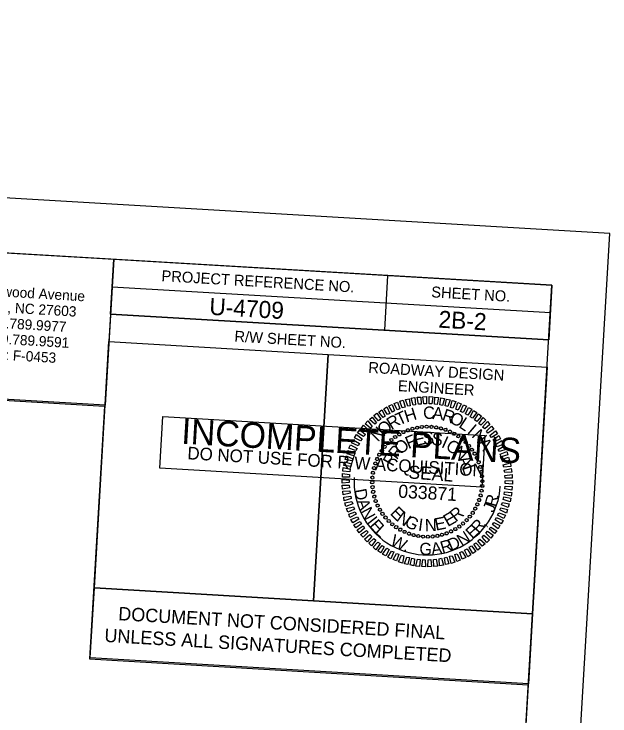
# Model space of a CAD drawing. Extents: x 2012744 to 2013625, y 444638 to 445237.
# Drawn here: x 2013488.7 to 2013624.5, y 445076.8 to 445236.8 of the extents above; entities that cross this region are included whole.
import ezdxf

# ---------------------------------------------------------------- set-up
doc = ezdxf.new("R2010")
doc.units = 0
for name, color, linetype in [('Old_Level_2', 7, 'Continuous'), ('Old_Level_58', 7, 'Continuous'), ('Scratch_Level_0', 7, 'Continuous'), ('Sheet Clip Boundary CELL', 7, 'Continuous'), ('Sheet Data Field CELL', 7, 'Continuous'), ('Sheet Plan And Profile CELL', 7, 'Continuous'), ('Sheet Plot Border Outside CELL', 7, 'Continuous'), ('Sheet Professional Seal CELL', 7, 'Continuous'), ('Sheet Profile Grid Minor CELL', 7, 'Continuous'), ('Sheet Sticker Exception Certification CELL', 7, 'Continuous'), ('Sheet Sticker Incomplete CELL', 7, 'Continuous')]:
    doc.layers.add(name, color=color, linetype=linetype)

msp = doc.modelspace()

# ---------------------------------------------------------------- linework, layer by layer
at = {"layer": 'Old_Level_58'}
msp.add_lwpolyline([(2013411.6, 445186.8), (2013511.45, 445180.92), (2013509.49, 445147.63), (2013409.64, 445153.51)], close=True, dxfattribs=at)
at = {"layer": 'Scratch_Level_0'}
msp.add_arc((2013582.88, 445130.21), 16.68, 176.6264, 356.6264, dxfattribs=at)
at = {"layer": 'Sheet Clip Boundary CELL'}
for points in [[(2013605.95, 445084.18), (2013506.09, 445090.07), (2013509.49, 445147.63), (2013409.64, 445153.51), (2013411.6, 445186.8), (2012862.6, 445219.16), (2012831.71, 444695.07), (2013580.41, 444650.94)], [(2012832.37, 444695.56), (2012863.22, 445218.85), (2013411.41, 445186.54), (2013409.45, 445153.34), (2013509.31, 445147.45), (2013505.92, 445089.85), (2013605.86, 445083.96), (2013580.34, 444651.05)]]:
    msp.add_lwpolyline(points, close=True, dxfattribs=at)
at = {"layer": 'Sheet Plan And Profile CELL'}
for p, q in [((2013573.86, 445177.21), (2013573.13, 445164.73)), ((2013511.08, 445174.65), (2013610.93, 445168.77)), ((2013510.71, 445168.41), (2013510.34, 445162.17)), ((2013510.71, 445168.41), (2013610.56, 445162.53)), ((2013560.28, 445159.23), (2013556.97, 445103.1))]:
    msp.add_line(p, q, dxfattribs=at)
for points in [[(2013611.3, 445175.03), (2012862.6, 445219.16), (2012831.71, 444695.07), (2013580.41, 444650.94)], [(2013511.45, 445180.92), (2013611.3, 445175.03), (2013610.56, 445162.53), (2013510.71, 445168.41)], [(2013510.34, 445162.17), (2013560.28, 445159.23), (2013556.97, 445103.08), (2013507.03, 445106.02)], [(2013560.28, 445159.23), (2013610.2, 445156.29), (2013606.89, 445100.13), (2013556.97, 445103.08)]]:
    msp.add_lwpolyline(points, close=True, dxfattribs=at)
at = {"layer": 'Sheet Plot Border Outside CELL'}
msp.add_lwpolyline([(2012743.62, 444687.74), (2013592.15, 444637.73), (2013624.51, 445186.77), (2012775.99, 445236.79)], close=True, dxfattribs=at)
at = {"layer": 'Sheet Professional Seal CELL'}
for p, q in [((2013577.47, 445141.52), (2013577.47, 445141.52)), ((2013578.47, 445141.96), (2013578.47, 445141.96)), ((2013579.49, 445142.3), (2013579.49, 445142.3)), ((2013580.56, 445142.54), (2013580.56, 445142.54)), ((2013581.67, 445142.68), (2013581.67, 445142.68)), ((2013582.75, 445142.76), (2013582.75, 445142.76)), ((2013583.85, 445142.72), (2013583.85, 445142.72)), ((2013584.94, 445142.58), (2013584.94, 445142.58)), ((2013586, 445142.35), (2013586, 445142.35)), ((2013587.04, 445142.06), (2013587.04, 445142.06)), ((2013588.07, 445141.65), (2013588.07, 445141.65)), ((2013575.57, 445140.43), (2013575.57, 445140.43)), ((2013576.48, 445141), (2013576.48, 445141)), ((2013589.04, 445141.14), (2013589.04, 445141.14)), ((2013589.98, 445140.58), (2013589.98, 445140.58)), ((2013590.84, 445139.91), (2013590.84, 445139.91)), ((2013573.91, 445139), (2013573.91, 445139)), ((2013574.71, 445139.73), (2013574.71, 445139.73)), ((2013591.68, 445139.18), (2013591.68, 445139.18)), ((2013592.41, 445138.39), (2013592.41, 445138.39)), ((2013572.51, 445137.31), (2013572.51, 445137.31)), ((2013573.19, 445138.17), (2013573.19, 445138.17)), ((2013593.11, 445137.52), (2013593.11, 445137.52)), ((2013593.68, 445136.61), (2013593.68, 445136.61)), ((2013571.45, 445135.39), (2013571.45, 445135.39)), ((2013571.95, 445136.36), (2013571.95, 445136.36)), ((2013594.2, 445135.63), (2013594.2, 445135.63)), ((2013571.03, 445134.36), (2013571.03, 445134.36)), ((2013594.64, 445134.62), (2013594.64, 445134.62)), ((2013594.98, 445133.6), (2013594.98, 445133.6)), ((2013570.51, 445132.26), (2013570.51, 445132.26)), ((2013570.75, 445133.33), (2013570.75, 445133.33)), ((2013595.22, 445132.54), (2013595.22, 445132.54)), ((2013570.37, 445131.17), (2013570.37, 445131.17)), ((2013582.88, 445130.21), (2013582.88, 445130.21)), ((2013595.35, 445131.43), (2013595.35, 445131.43)), ((2013595.44, 445130.34), (2013595.44, 445130.34)), ((2013570.33, 445130.07), (2013570.33, 445130.07)), ((2013570.42, 445128.99), (2013570.42, 445128.99)), ((2013595.4, 445129.24), (2013595.4, 445129.24)), ((2013570.55, 445127.88), (2013570.55, 445127.88)), ((2013595.02, 445127.09), (2013595.02, 445127.09)), ((2013595.26, 445128.15), (2013595.26, 445128.15)), ((2013570.79, 445126.81), (2013570.79, 445126.81)), ((2013571.13, 445125.79), (2013571.13, 445125.79)), ((2013594.74, 445126.05), (2013594.74, 445126.05)), ((2013571.57, 445124.79), (2013571.57, 445124.79)), ((2013572.09, 445123.81), (2013572.09, 445123.81)), ((2013593.82, 445124.05), (2013593.82, 445124.05)), ((2013594.32, 445125.03), (2013594.32, 445125.03)), ((2013572.66, 445122.9), (2013572.66, 445122.9)), ((2013592.58, 445122.25), (2013592.58, 445122.25)), ((2013593.26, 445123.11), (2013593.26, 445123.11)), ((2013573.36, 445122.03), (2013573.36, 445122.03)), ((2013574.09, 445121.23), (2013574.09, 445121.23)), ((2013591.06, 445120.68), (2013591.06, 445120.68)), ((2013591.86, 445121.41), (2013591.86, 445121.41)), ((2013574.93, 445120.51), (2013574.93, 445120.51)), ((2013575.79, 445119.83), (2013575.79, 445119.83)), ((2013576.73, 445119.28), (2013576.73, 445119.28)), ((2013589.29, 445119.41), (2013589.29, 445119.41)), ((2013590.2, 445119.98), (2013590.2, 445119.98)), ((2013577.7, 445118.77), (2013577.7, 445118.77)), ((2013578.73, 445118.36), (2013578.73, 445118.36)), ((2013579.77, 445118.07), (2013579.77, 445118.07)), ((2013580.83, 445117.83), (2013580.83, 445117.83)), ((2013581.92, 445117.69), (2013581.92, 445117.69)), ((2013583.02, 445117.65), (2013583.02, 445117.65)), ((2013584.1, 445117.74), (2013584.1, 445117.74)), ((2013585.21, 445117.87), (2013585.21, 445117.87)), ((2013586.28, 445118.11), (2013586.28, 445118.11)), ((2013587.3, 445118.45), (2013587.3, 445118.45)), ((2013588.3, 445118.89), (2013588.3, 445118.89))]:
    msp.add_line(p, q, dxfattribs=at)
for points in [[(2013580.87, 445147.86), (2013580.56, 445149.48), (2013581.39, 445149.5), (2013581.47, 445147.9)], [(2013582.08, 445147.94), (2013581.9, 445149.55), (2013582.75, 445149.6), (2013582.68, 445147.98)], [(2013583.33, 445147.99), (2013583.3, 445149.62), (2013584.12, 445149.54), (2013583.93, 445147.93)], [(2013584.53, 445147.89), (2013584.62, 445149.51), (2013585.45, 445149.44), (2013585.13, 445147.83)], [(2013574.96, 445146.08), (2013574.11, 445147.48), (2013574.91, 445147.83), (2013575.45, 445146.35)], [(2013576.06, 445146.61), (2013575.35, 445148.06), (2013576.14, 445148.36), (2013576.63, 445146.8)], [(2013577.19, 445147.07), (2013576.63, 445148.56), (2013577.4, 445148.81), (2013577.83, 445147.18)], [(2013578.44, 445147.4), (2013577.95, 445148.93), (2013578.74, 445149.11), (2013578.97, 445147.54)], [(2013579.66, 445147.65), (2013579.22, 445149.26), (2013580.08, 445149.38), (2013580.19, 445147.75)], [(2013585.77, 445147.74), (2013585.97, 445149.36), (2013586.78, 445149.16), (2013586.36, 445147.61)], [(2013586.96, 445147.47), (2013587.28, 445149.06), (2013588.09, 445148.88), (2013587.55, 445147.36)], [(2013588.21, 445147.12), (2013588.56, 445148.73), (2013589.4, 445148.48), (2013588.73, 445146.97)], [(2013589.39, 445146.73), (2013589.86, 445148.25), (2013590.62, 445147.96), (2013589.91, 445146.52)], [(2013572.83, 445144.82), (2013571.83, 445146.09), (2013572.53, 445146.57), (2013573.32, 445145.12)], [(2013573.82, 445145.52), (2013572.97, 445146.84), (2013573.65, 445147.28), (2013574.39, 445145.78)], [(2013590.49, 445146.21), (2013591.16, 445147.75), (2013591.84, 445147.41), (2013591.05, 445146)], [(2013591.59, 445145.67), (2013592.3, 445147.11), (2013593.05, 445146.71), (2013592.12, 445145.37)], [(2013592.7, 445145.03), (2013593.46, 445146.41), (2013594.18, 445145.95), (2013593.16, 445144.7)], [(2013570.91, 445143.29), (2013569.7, 445144.38), (2013570.35, 445144.92), (2013571.33, 445143.66)], [(2013571.78, 445144.11), (2013570.75, 445145.27), (2013571.38, 445145.84), (2013572.28, 445144.43)], [(2013593.63, 445144.3), (2013594.59, 445145.7), (2013595.21, 445145.13), (2013594.16, 445143.97)], [(2013594.61, 445143.49), (2013595.62, 445144.81), (2013596.23, 445144.22), (2013595.07, 445143.11)], [(2013569.17, 445141.48), (2013567.88, 445142.41), (2013568.39, 445143.11), (2013569.53, 445141.94)], [(2013569.98, 445142.39), (2013568.74, 445143.44), (2013569.33, 445144.05), (2013570.36, 445142.82)], [(2013595.51, 445142.66), (2013596.61, 445143.9), (2013597.18, 445143.26), (2013595.97, 445142.26)], [(2013568.37, 445140.53), (2013567.01, 445141.36), (2013567.55, 445142.03), (2013568.79, 445140.96)], [(2013596.36, 445141.73), (2013597.5, 445142.84), (2013598.07, 445142.21), (2013596.71, 445141.31)], [(2013597.18, 445140.78), (2013598.4, 445141.84), (2013598.88, 445141.14), (2013597.5, 445140.26)], [(2013567.71, 445139.49), (2013566.32, 445140.2), (2013566.74, 445140.95), (2013568.03, 445139.95)], [(2013597.87, 445139.77), (2013599.16, 445140.74), (2013599.59, 445139.99), (2013598.15, 445139.28)], [(2013566.57, 445137.3), (2013565.05, 445137.85), (2013565.42, 445138.6), (2013566.88, 445137.81)], [(2013567.14, 445138.37), (2013565.62, 445139.04), (2013566.04, 445139.79), (2013567.42, 445138.91)], [(2013598.46, 445138.71), (2013599.84, 445139.58), (2013600.27, 445138.8), (2013598.78, 445138.19)], [(2013599.05, 445137.57), (2013600.5, 445138.36), (2013600.77, 445137.57), (2013599.32, 445137.08)], [(2013566.13, 445136.13), (2013564.6, 445136.54), (2013564.82, 445137.36), (2013566.36, 445136.64)], [(2013599.48, 445136.47), (2013601, 445137.13), (2013601.28, 445136.31), (2013599.7, 445135.9)], [(2013565.73, 445134.95), (2013564.2, 445135.24), (2013564.42, 445136.08), (2013565.96, 445135.46)], [(2013599.86, 445135.27), (2013601.42, 445135.83), (2013601.65, 445135.04), (2013600.08, 445134.73)], [(2013565.26, 445132.5), (2013563.64, 445132.64), (2013563.74, 445133.46), (2013565.35, 445133.09)], [(2013565.46, 445133.69), (2013563.87, 445133.93), (2013564.02, 445134.78), (2013565.62, 445134.28)], [(2013600.19, 445134.05), (2013601.82, 445134.53), (2013601.92, 445133.69), (2013600.33, 445133.51)], [(2013565.17, 445131.25), (2013563.54, 445131.27), (2013563.59, 445132.12), (2013565.2, 445131.85)], [(2013600.42, 445132.83), (2013602.02, 445133.21), (2013602.12, 445132.35), (2013600.54, 445132.3)], [(2013600.57, 445131.62), (2013602.22, 445131.87), (2013602.24, 445131.02), (2013600.64, 445131.01)], [(2013565.12, 445130), (2013563.48, 445129.9), (2013563.48, 445130.75), (2013565.1, 445130.6)], [(2013600.65, 445130.41), (2013602.29, 445130.52), (2013602.29, 445129.66), (2013600.67, 445129.81)], [(2013565.2, 445128.8), (2013563.55, 445128.54), (2013563.53, 445129.4), (2013565.13, 445129.4)], [(2013600.6, 445129.16), (2013602.23, 445129.14), (2013602.18, 445128.29), (2013600.57, 445128.56)], [(2013565.35, 445127.58), (2013563.75, 445127.2), (2013563.65, 445128.06), (2013565.23, 445128.12)], [(2013600.51, 445127.92), (2013602.12, 445127.77), (2013602.03, 445126.95), (2013600.42, 445127.32)], [(2013565.58, 445126.37), (2013563.95, 445125.89), (2013563.85, 445126.72), (2013565.44, 445126.9)], [(2013565.91, 445125.15), (2013564.35, 445124.59), (2013564.12, 445125.38), (2013565.69, 445125.69)], [(2013600.04, 445125.47), (2013601.57, 445125.17), (2013601.35, 445124.34), (2013599.81, 445124.95)], [(2013600.31, 445126.73), (2013601.9, 445126.48), (2013601.75, 445125.64), (2013600.15, 445126.13)], [(2013566.29, 445123.95), (2013564.77, 445123.29), (2013564.49, 445124.1), (2013566.07, 445124.51)], [(2013599.64, 445124.29), (2013601.17, 445123.87), (2013600.95, 445123.06), (2013599.41, 445123.77)], [(2013566.72, 445122.85), (2013565.27, 445122.05), (2013565, 445122.85), (2013566.45, 445123.34)], [(2013567.31, 445121.71), (2013565.93, 445120.84), (2013565.5, 445121.62), (2013566.99, 445122.23)], [(2013599.2, 445123.11), (2013600.72, 445122.57), (2013600.35, 445121.82), (2013598.89, 445122.6)], [(2013567.9, 445120.65), (2013566.61, 445119.67), (2013566.18, 445120.42), (2013567.62, 445121.14)], [(2013598.06, 445120.92), (2013599.45, 445120.22), (2013599.03, 445119.46), (2013597.74, 445120.47)], [(2013598.63, 445122.04), (2013600.15, 445121.38), (2013599.73, 445120.63), (2013598.35, 445121.51)], [(2013568.59, 445119.63), (2013567.37, 445118.58), (2013566.89, 445119.28), (2013568.27, 445120.15)], [(2013569.41, 445118.68), (2013568.27, 445117.57), (2013567.7, 445118.21), (2013569.06, 445119.1)], [(2013597.4, 445119.89), (2013598.76, 445119.05), (2013598.22, 445118.38), (2013596.98, 445119.46)], [(2013570.26, 445117.75), (2013569.16, 445116.52), (2013568.59, 445117.15), (2013569.8, 445118.16)], [(2013595.79, 445118.03), (2013597.03, 445116.98), (2013596.44, 445116.36), (2013595.41, 445117.6)], [(2013596.6, 445118.93), (2013597.89, 445118), (2013597.38, 445117.31), (2013596.24, 445118.48)], [(2013571.16, 445116.92), (2013570.15, 445115.61), (2013569.54, 445116.19), (2013570.7, 445117.3)], [(2013572.14, 445116.12), (2013571.18, 445114.72), (2013570.56, 445115.28), (2013571.61, 445116.45)], [(2013593.99, 445116.31), (2013595.02, 445115.14), (2013594.39, 445114.58), (2013593.49, 445115.98)], [(2013594.86, 445117.13), (2013596.07, 445116.03), (2013595.42, 445115.49), (2013594.44, 445116.75)], [(2013573.07, 445115.38), (2013572.31, 445114), (2013571.59, 445114.47), (2013572.61, 445115.71)], [(2013574.18, 445114.74), (2013573.47, 445113.31), (2013572.72, 445113.7), (2013573.65, 445115.05)], [(2013575.28, 445114.2), (2013574.61, 445112.66), (2013573.93, 445113), (2013574.72, 445114.41)], [(2013590.81, 445114.34), (2013591.66, 445112.94), (2013590.86, 445112.58), (2013590.32, 445114.07)], [(2013591.95, 445114.9), (2013592.8, 445113.57), (2013592.12, 445113.13), (2013591.38, 445114.63)], [(2013592.94, 445115.59), (2013593.94, 445114.33), (2013593.24, 445113.84), (2013592.45, 445115.29)], [(2013576.38, 445113.69), (2013575.91, 445112.16), (2013575.15, 445112.46), (2013575.86, 445113.89)], [(2013577.56, 445113.29), (2013577.21, 445111.68), (2013576.37, 445111.93), (2013577.04, 445113.45)], [(2013578.81, 445112.94), (2013578.49, 445111.36), (2013577.68, 445111.53), (2013578.22, 445113.05)], [(2013580, 445112.67), (2013579.8, 445111.06), (2013578.99, 445111.25), (2013579.4, 445112.81)], [(2013586.11, 445112.76), (2013586.55, 445111.16), (2013585.69, 445111.03), (2013585.58, 445112.67)], [(2013587.33, 445113.02), (2013587.82, 445111.48), (2013587.03, 445111.31), (2013586.8, 445112.87)], [(2013588.58, 445113.34), (2013589.14, 445111.86), (2013588.37, 445111.6), (2013587.94, 445113.23)], [(2013589.71, 445113.8), (2013590.42, 445112.36), (2013589.63, 445112.05), (2013589.14, 445113.61)], [(2013581.24, 445112.52), (2013581.15, 445110.9), (2013580.32, 445110.97), (2013580.64, 445112.58)], [(2013582.44, 445112.43), (2013582.47, 445110.8), (2013581.64, 445110.87), (2013581.84, 445112.49)], [(2013583.69, 445112.48), (2013583.87, 445110.87), (2013583.02, 445110.82), (2013583.09, 445112.44)], [(2013584.9, 445112.56), (2013585.21, 445110.94), (2013584.38, 445110.91), (2013584.3, 445112.52)]]:
    msp.add_lwpolyline(points, close=True, dxfattribs=at)
for centre, major_axis in [((2013581.66, 445142.69), (-0.035, 0.358)), ((2013582.75, 445142.75), (-0.004, 0.36)), ((2013583.84, 445142.71), (0.027, 0.359)), ((2013576.5, 445141), (-0.183, 0.31)), ((2013577.46, 445141.51), (-0.156, 0.325)), ((2013578.47, 445141.94), (-0.127, 0.337)), ((2013579.51, 445142.28), (-0.097, 0.347)), ((2013580.57, 445142.53), (-0.066, 0.354)), ((2013584.93, 445142.58), (0.059, 0.355)), ((2013586, 445142.36), (0.089, 0.349)), ((2013587.04, 445142.04), (0.119, 0.34)), ((2013588.06, 445141.63), (0.149, 0.328)), ((2013589.04, 445141.14), (0.177, 0.314)), ((2013574.72, 445139.73), (-0.234, 0.273)), ((2013575.58, 445140.4), (-0.21, 0.293)), ((2013589.96, 445140.56), (0.203, 0.297)), ((2013590.84, 445139.9), (0.228, 0.278)), ((2013573.19, 445138.16), (-0.278, 0.228)), ((2013573.92, 445138.98), (-0.257, 0.252)), ((2013591.65, 445139.17), (0.252, 0.257)), ((2013592.4, 445138.37), (0.273, 0.234)), ((2013571.96, 445136.36), (-0.314, 0.177)), ((2013572.53, 445137.29), (-0.297, 0.203)), ((2013593.08, 445137.51), (0.293, 0.21)), ((2013593.68, 445136.6), (0.31, 0.183)), ((2013571.46, 445135.38), (-0.328, 0.149)), ((2013594.19, 445135.63), (0.325, 0.156)), ((2013594.62, 445134.63), (0.337, 0.127)), ((2013570.74, 445133.32), (-0.349, 0.089)), ((2013571.06, 445134.37), (-0.34, 0.119)), ((2013594.96, 445133.59), (0.347, 0.097)), ((2013570.51, 445132.25), (-0.355, 0.059)), ((2013595.21, 445132.52), (0.354, 0.066)), ((2013595.36, 445131.44), (0.358, 0.035)), ((2013570.35, 445130.07), (-0.36, -0.004)), ((2013570.38, 445131.16), (-0.359, 0.027)), ((2013595.42, 445130.34), (0.36, 0.004)), ((2013570.41, 445128.98), (-0.358, -0.035)), ((2013595.39, 445129.25), (0.359, -0.027)), ((2013570.56, 445127.9), (-0.354, -0.066)), ((2013570.81, 445126.83), (-0.347, -0.097)), ((2013595.03, 445127.09), (0.349, -0.089)), ((2013595.26, 445128.17), (0.355, -0.059)), ((2013571.15, 445125.79), (-0.337, -0.127)), ((2013594.31, 445125.03), (0.328, -0.149)), ((2013594.71, 445126.05), (0.34, -0.119)), ((2013571.58, 445124.78), (-0.325, -0.156)), ((2013572.09, 445123.82), (-0.31, -0.183)), ((2013593.81, 445124.06), (0.314, -0.177)), ((2013572.69, 445122.9), (-0.293, -0.21)), ((2013573.37, 445122.04), (-0.273, -0.234)), ((2013592.58, 445122.25), (0.278, -0.228)), ((2013593.24, 445123.13), (0.297, -0.203)), ((2013574.12, 445121.24), (-0.252, -0.257)), ((2013574.93, 445120.51), (-0.228, -0.278)), ((2013591.05, 445120.69), (0.234, -0.273)), ((2013591.85, 445121.44), (0.257, -0.252)), ((2013575.81, 445119.86), (-0.203, -0.297)), ((2013576.73, 445119.28), (-0.177, -0.314)), ((2013577.71, 445118.79), (-0.149, -0.328)), ((2013588.31, 445118.9), (0.156, -0.325)), ((2013589.27, 445119.42), (0.183, -0.31)), ((2013590.19, 445120.01), (0.21, -0.293)), ((2013578.73, 445118.38), (-0.119, -0.34)), ((2013579.77, 445118.06), (-0.089, -0.349)), ((2013580.84, 445117.84), (-0.059, -0.355)), ((2013581.93, 445117.7), (-0.027, -0.359)), ((2013583.02, 445117.67), (0.004, -0.36)), ((2013584.11, 445117.73), (0.035, -0.358)), ((2013585.2, 445117.88), (0.066, -0.354)), ((2013586.26, 445118.13), (0.097, -0.347)), ((2013587.3, 445118.47), (0.127, -0.337))]:
    msp.add_ellipse(centre, major_axis=major_axis, ratio=0.999708, dxfattribs=at)
at = {"layer": 'Sheet Sticker Exception Certification CELL'}
for p, q in [((2013506.09, 445090.07), (2013507.03, 445106.03)), ((2013507.03, 445106.03), (2013606.89, 445100.14)), ((2013606.89, 445100.13), (2013605.94, 445084.17)), ((2013605.95, 445084.18), (2013506.09, 445090.07))]:
    msp.add_line(p, q, dxfattribs=at)
at = {"layer": 'Sheet Sticker Incomplete CELL'}
msp.add_lwpolyline([(2013521.94, 445133.32), (2013522.63, 445145.05), (2013596.01, 445140.72), (2013595.31, 445128.99)], close=True, dxfattribs=at)

# ---------------------------------------------------------------- texts
at = {"layer": 'Old_Level_2'}
for s, p in [('1 Glenwood Avenue', (2013476.82, 445172.96)), ('Raleigh, NC 27603', (2013476.61, 445169.37)), ('Tel:919.789.9977 ', (2013476.4, 445165.77)), ('Fax:919.789.9591', (2013476.18, 445162.18)), ('License: F-0453', (2013475.97, 445158.59))]:
    msp.add_text(s, height=2.3288, rotation=356.6264, dxfattribs=at).set_placement(p)
at = {"layer": 'Sheet Data Field CELL'}
for s, p in [('U-4709', (2013533.14, 445168.27)), ('2B-2', (2013585.36, 445165.34))]:
    msp.add_text(s, height=3.875, rotation=356.6264, dxfattribs=at).set_placement(p)
at = {"layer": 'Sheet Plan And Profile CELL'}
for s, p in [('PROJECT REFERENCE NO.', (2013522.27, 445175.92)), ('SHEET NO.', (2013583.74, 445172.25)), ('R/W SHEET NO.', (2013538.89, 445162.14)), ('ROADWAY DESIGN', (2013569.4, 445155.04)), ('ENGINEER', (2013576.14, 445150.86))]:
    msp.add_text(s, height=2.5, rotation=356.6264, dxfattribs=at).set_placement(p)
at = {"layer": 'Sheet Professional Seal CELL'}
for s, height, rotation, p in [('T', 2.82, 24.4462, (2013576.47, 445142.96)), ('H', 2.82, 17.2459, (2013578.14, 445143.68)), ('C', 2.82, 2.8463, (2013582, 445144.46)), ('A', 2.82, 355.6467, (2013583.98, 445144.49)), ('R', 2.82, 341.2475, (2013586.07, 445144.27)), ('R', 2.82, 31.6469, (2013574.71, 445141.96)), ('O', 2.82, 334.0476, (2013587.72, 445143.8)), ('L', 2.82, 326.8473, (2013589.86, 445142.74)), ('O', 2.82, 38.8482, (2013572.9, 445140.51)), ('I', 2.82, 319.6466, (2013591.81, 445141.43)), ('N', 2.82, 46.0499, (2013571.67, 445139.13)), ('E', 2.82, 13.2375, (2013580.23, 445138.28)), ('S', 2.82, 3.882, (2013581.98, 445138.7)), ('N', 2.82, 312.4453, (2013592.84, 445140.59)), ('F', 2.82, 22.5935, (2013578.59, 445137.62)), ('S', 2.82, 354.5268, (2013583.78, 445138.62)), ('I', 2.82, 335.816, (2013585.91, 445138.14)), ('R', 2.82, 50.6661, (2013575.91, 445135.08)), ('O', 2.82, 41.3077, (2013576.85, 445136.25)), ('O', 2.82, 326.4599, (2013586.88, 445137.74)), ('N', 2.82, 317.103, (2013588.5, 445136.64)), ('A', 2.82, 305.2436, (2013594.22, 445139.03)), ('P', 2.82, 60.0253, (2013575.02, 445133.53)), ('A', 2.82, 298.3867, (2013589.84, 445135.26)), ('SEAL', 2.999, 355.6264, (2013578.5, 445130.97)), ('L', 2.82, 289.0273, (2013590.72, 445133.48)), ('E', 2.82, 314.9033, (2013574.24, 445122.88)), ('R', 2.82, 39.1078, (2013589.4, 445120.93)), ('N', 2.82, 324.2604, (2013575.66, 445121.44)), ('G', 2.82, 333.6167, (2013577.49, 445120.21)), ('E', 2.82, 11.0382, (2013584.86, 445119.05)), ('E', 2.82, 29.7505, (2013587.56, 445119.86)), ('I', 2.82, 352.3276, (2013580.7, 445119.07)), ('N', 2.82, 1.6828, (2013582.37, 445118.89))]:
    msp.add_text(s, height=height, rotation=rotation, dxfattribs=at).set_placement(p)
at = {"layer": 'Sheet Profile Grid Minor CELL'}
for s, height, rotation, p in [('033871', 2.999, 356.6264, (2013576.21, 445126.59)), ('D', 2.75, 280.8946, (2013566.25, 445128.36)), ('R', 2.75, 73.9805, (2013598.55, 445124.32)), ('.', 2.75, 80.9069, (2013599.15, 445126.26)), ('A', 2.75, 290.0393, (2013566.76, 445125.74)), ('J', 2.75, 69.1119, (2013598, 445123.02)), ('N', 2.75, 298.2251, (2013567.56, 445123.49)), ('I', 2.75, 308.1568, (2013568.95, 445120.95)), ('E', 2.75, 311.6772, (2013569.54, 445120.11)), ('R', 2.75, 49.0052, (2013594.6, 445118.26)), ('L', 2.75, 318.2602, (2013570.79, 445118.65)), ('N', 2.75, 32.4905, (2013590.72, 445115.42)), ('E', 2.75, 42.4222, (2013593.16, 445117)), (',', 2.75, 55.9317, (2013595.96, 445119.76)), ('W', 2.75, 333.5156, (2013574.25, 445115.87)), ('D', 2.75, 23.3459, (2013588.27, 445114.36)), ('G', 2.75, 358.3019, (2013581.06, 445113.57)), ('A', 2.75, 8.2337, (2013583.96, 445113.51)), ('R', 2.75, 16.4194, (2013586.32, 445113.83)), ('.', 2.75, 345.1217, (2013577.31, 445114.43))]:
    msp.add_text(s, height=height, rotation=rotation, dxfattribs=at).set_placement(p)
at = {"layer": 'Sheet Sticker Exception Certification CELL'}
for s, p in [('DOCUMENT NOT CONSIDERED FINAL', (2013512.42, 445098.66)), ('UNLESS ALL SIGNATURES COMPLETED', (2013509.26, 445093.71))]:
    msp.add_text(s, height=3.062, rotation=356.6264, dxfattribs=at).set_placement(p)
at = {"layer": 'Sheet Sticker Incomplete CELL'}
for s, height, p in [('INCOMPLETE PLANS', 5.76, (2013526.75, 445138.89)), ('DO NOT USE FOR R/W ACQUISITION', 2.88, (2013528.17, 445135.33))]:
    msp.add_text(s, height=height, rotation=356.6264, dxfattribs=at).set_placement(p)

doc.saveas('drawing.dxf')
